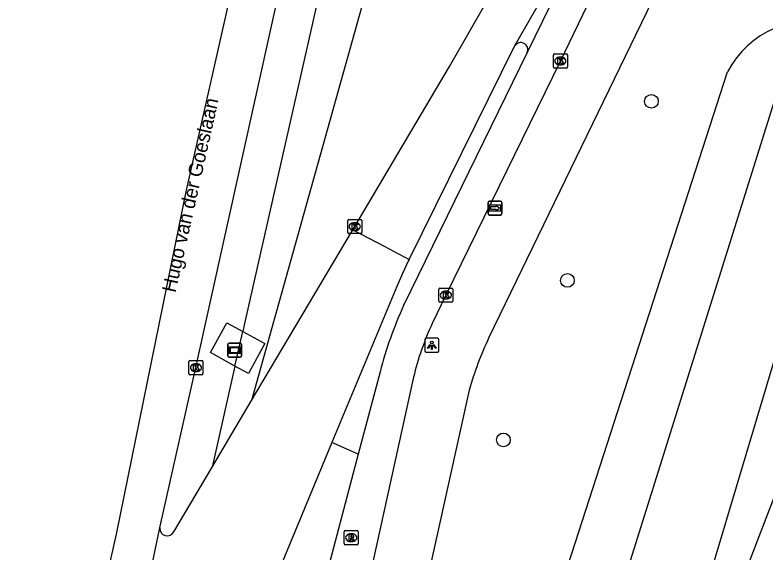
# Model space of a CAD drawing. Extents: x 163046 to 165074, y 382019 to 382874.
# Drawn here: x 163047.3 to 163100.8, y 382537 to 382575.3 of the extents above; entities that cross this region are included whole.
import ezdxf

# ---------------------------------------------------------------- set-up
doc = ezdxf.new("R2010")
doc.units = 0
for name, color, linetype in [('IMGEO_Berm_groen', 7, 'Continuous'), ('IMGEO_Boom', 7, 'Continuous'), ('IMGEO_Erf', 7, 'Continuous'), ('IMGEO_Fietspad_open', 7, 'Continuous'), ('IMGEO_Kolk', 7, 'Continuous'), ('IMGEO_Lichtpunt', 7, 'Continuous'), ('IMGEO_Openbare_ruimte_label', 7, 'Continuous'), ('IMGEO_Reclamebord', 7, 'Continuous'), ('IMGEO_Rijbaan_lokaal_gesloten', 7, 'Continuous'), ('IMGEO_Rijbaan_lokaal_open', 7, 'Continuous'), ('IMGEO_Rijbaan_regionaal_gesloten', 7, 'Continuous'), ('IMGEO_Rioolput', 7, 'Continuous'), ('IMGEO_Verkeerseiland_open', 7, 'Continuous'), ('IMGEO_Voetpad_open', 7, 'Continuous'), ('IMGEO_Waterloop', 7, 'Continuous'), ('IMGEO_Wegwijzer', 7, 'Continuous')]:
    doc.layers.add(name, color=color, linetype=linetype)

msp = doc.modelspace()

# ---------------------------------------------------------------- linework, layer by layer
at = {"layer": 'IMGEO_Berm_groen'}
for points in [[(163093.932, 382685.896), (163093.759, 382685.284), (163092.671, 382681.431), (163063.671, 382553.383), (163063.543, 382552.818)], [(163100.832, 382683.6), (163098.443, 382676.291), (163089.933, 382645.473), (163080.796, 382607.304), (163064.17, 382547.891)], [(163079.41, 382513.579), (163098.094, 382571.31)], [(163062.985, 382550.353), (163061.352, 382543.143)]]:
    msp.add_lwpolyline(points, dxfattribs=at)
msp.add_arc((163104.154, 382568.109), 6.853, 74.8139, 152.1561, dxfattribs=at)
at = {"layer": 'IMGEO_Boom'}
for centre in [(163092.668, 382569.203), (163086.678, 382556.45), (163082.117, 382545.088)]:
    msp.add_circle(centre, 0.489, dxfattribs=at)
at = {"layer": 'IMGEO_Erf'}
msp.add_lwpolyline([(163110.796, 382567.221), (163110.13, 382565.257), (163109.52, 382565.45), (163107.111, 382557.948), (163103.756, 382547.756), (163102.319, 382543.379), (163096.566, 382528.425), (163091.564, 382511.556)], dxfattribs=at)
at = {"layer": 'IMGEO_Fietspad_open'}
for points in [[(163090.329, 382586.006), (163083.814, 382572.678)], [(163092.391, 382584.969), (163091.883, 382583.941), (163086.165, 382572.05), (163078.013, 382555.397), (163077.04, 382553.381)], [(163083.814, 382572.678), (163075.006, 382554.656)], [(163073.328, 382549.944), (163071.757, 382544.071)], [(163075.706, 382549.562), (163070.131, 382524.198), (163067.388, 382511.786), (163064.83, 382500), (163063.356, 382493.212)], [(163071.757, 382544.071), (163069.665, 382536.151), (163067.191, 382524.864), (163064.403, 382512.197), (163062.59, 382503.776), (163061.753, 382500), (163060.171, 382492.863)]]:
    msp.add_lwpolyline(points, dxfattribs=at)
for centre, radius, start, end in [((163100.06, 382543.079), 27.599, 155.1995, 165.5977), ((163097.064, 382544.244), 22.01, 155.4726, 166.0182)]:
    msp.add_arc(centre, radius, start, end, dxfattribs=at)
at = {"layer": 'IMGEO_Kolk'}
for p, q in [((163085.677, 382571.649), (163085.677, 382572.501)), ((163085.752, 382572.575), (163086.604, 382572.575)), ((163086.165, 382572.355), (163086.19, 382572.355)), ((163086.678, 382572.501), (163086.678, 382571.649)), ((163086.188, 382571.795), (163086.163, 382571.795)), ((163086.604, 382571.575), (163085.752, 382571.575)), ((163071.02, 382559.854), (163071.02, 382560.706)), ((163071.095, 382560.78), (163071.947, 382560.78)), ((163071.508, 382560.56), (163071.533, 382560.56)), ((163072.021, 382560.706), (163072.021, 382559.854)), ((163071.531, 382560), (163071.506, 382560)), ((163071.947, 382559.78), (163071.095, 382559.78)), ((163077.517, 382554.98), (163077.517, 382555.832)), ((163077.592, 382555.906), (163078.444, 382555.906)), ((163078.518, 382555.832), (163078.518, 382554.98)), ((163078.005, 382555.686), (163078.03, 382555.686)), ((163078.444, 382554.906), (163077.592, 382554.906)), ((163078.028, 382555.126), (163078.003, 382555.126)), ((163059.702, 382549.81), (163059.702, 382550.662)), ((163059.777, 382550.736), (163060.629, 382550.736)), ((163060.19, 382550.516), (163060.215, 382550.516)), ((163060.703, 382550.662), (163060.703, 382549.81)), ((163060.213, 382549.956), (163060.188, 382549.956)), ((163060.629, 382549.736), (163059.777, 382549.736))]:
    msp.add_line(p, q, dxfattribs=at)
for points in [[(163085.677, 382571.649), (163085.677, 382572.501)], [(163085.752, 382572.575), (163086.604, 382572.575)], [(163086.678, 382572.501), (163086.678, 382571.649)], [(163085.998, 382572.275), (163086.121, 382572.275), (163086.121, 382572.124), (163086.251, 382572.275), (163086.415, 382572.275), (163086.269, 382572.124), (163086.422, 382571.875), (163086.27, 382571.875), (163086.185, 382572.039), (163086.121, 382571.972), (163086.121, 382571.875), (163085.998, 382571.875), (163085.998, 382572.275)], [(163086.604, 382571.575), (163085.752, 382571.575)], [(163071.02, 382559.854), (163071.02, 382560.706)], [(163071.095, 382560.78), (163071.947, 382560.78)], [(163072.021, 382560.706), (163072.021, 382559.854)], [(163071.341, 382560.48), (163071.464, 382560.48), (163071.464, 382560.329), (163071.594, 382560.48), (163071.758, 382560.48), (163071.612, 382560.329), (163071.765, 382560.08), (163071.613, 382560.08), (163071.528, 382560.244), (163071.464, 382560.177), (163071.464, 382560.08), (163071.341, 382560.08), (163071.341, 382560.48)], [(163071.947, 382559.78), (163071.095, 382559.78)], [(163077.517, 382554.98), (163077.517, 382555.832)], [(163077.592, 382555.906), (163078.444, 382555.906)], [(163078.518, 382555.832), (163078.518, 382554.98)], [(163077.838, 382555.606), (163077.961, 382555.606), (163077.961, 382555.455), (163078.091, 382555.606), (163078.255, 382555.606), (163078.109, 382555.455), (163078.262, 382555.206), (163078.11, 382555.206), (163078.025, 382555.37), (163077.961, 382555.303), (163077.961, 382555.206), (163077.838, 382555.206), (163077.838, 382555.606)], [(163078.444, 382554.906), (163077.592, 382554.906)], [(163059.702, 382549.81), (163059.702, 382550.662)], [(163059.777, 382550.736), (163060.629, 382550.736)], [(163060.023, 382550.436), (163060.146, 382550.436), (163060.146, 382550.285), (163060.276, 382550.436), (163060.44, 382550.436), (163060.294, 382550.285), (163060.447, 382550.036), (163060.295, 382550.036), (163060.21, 382550.2), (163060.146, 382550.133), (163060.146, 382550.036), (163060.023, 382550.036), (163060.023, 382550.436)], [(163060.703, 382550.662), (163060.703, 382549.81)], [(163060.629, 382549.736), (163059.777, 382549.736)]]:
    msp.add_lwpolyline(points, dxfattribs=at)
for centre, start, end in [((163085.754, 382572.499), 91.552, 178.448), ((163085.754, 382572.499), 91.552, 178.448), ((163086.602, 382572.499), 1.552, 88.448), ((163086.602, 382572.499), 1.552, 88.448), ((163085.754, 382571.651), 181.552, 268.448), ((163085.754, 382571.651), 181.552, 268.448), ((163086.602, 382571.651), 271.552, 358.448), ((163086.602, 382571.651), 271.552, 358.448), ((163071.097, 382560.704), 91.552, 178.448), ((163071.097, 382560.704), 91.552, 178.448), ((163071.945, 382560.704), 1.552, 88.448), ((163071.945, 382560.704), 1.552, 88.448), ((163071.097, 382559.856), 181.552, 268.448), ((163071.097, 382559.856), 181.552, 268.448), ((163071.945, 382559.856), 271.552, 358.448), ((163071.945, 382559.856), 271.552, 358.448), ((163077.594, 382555.83), 91.552, 178.448), ((163077.594, 382555.83), 91.552, 178.448), ((163078.442, 382555.83), 1.552, 88.448), ((163078.442, 382555.83), 1.552, 88.448), ((163077.594, 382554.982), 181.552, 268.448), ((163077.594, 382554.982), 181.552, 268.448), ((163078.442, 382554.982), 271.552, 358.448), ((163078.442, 382554.982), 271.552, 358.448), ((163059.779, 382550.66), 91.552, 178.448), ((163059.779, 382550.66), 91.552, 178.448), ((163060.627, 382550.66), 1.552, 88.448), ((163060.627, 382550.66), 1.552, 88.448), ((163059.779, 382549.812), 181.552, 268.448), ((163059.779, 382549.812), 181.552, 268.448), ((163060.627, 382549.812), 271.552, 358.448), ((163060.627, 382549.812), 271.552, 358.448)]:
    msp.add_arc(centre, 0.0765, start, end, dxfattribs=at)
for centre, major_axis, ratio, start_param, end_param in [((163086.164, 382572.075), (-0.387, 0.002), 0.722429, 4.712389, 7.853982), ((163086.189, 382572.075), (-0.39, 0.002), 0.717154, 1.570796, 4.712389), ((163071.507, 382560.28), (-0.387, 0.002), 0.722429, 4.712389, 7.853982), ((163071.532, 382560.28), (-0.39, 0.002), 0.717154, 1.570796, 4.712389), ((163078.004, 382555.406), (-0.387, 0.002), 0.722429, 4.712389, 7.853982), ((163078.029, 382555.406), (-0.39, 0.002), 0.717154, 1.570796, 4.712389), ((163060.189, 382550.236), (-0.387, 0.002), 0.722429, 4.712389, 7.853982), ((163060.214, 382550.236), (-0.39, 0.002), 0.717154, 1.570796, 4.712389)]:
    msp.add_ellipse(centre, major_axis=major_axis, ratio=ratio, start_param=start_param, end_param=end_param, dxfattribs=at)
at = {"layer": 'IMGEO_Lichtpunt'}
for p, q in [((163076.519, 382552.232), (163076.519, 382551.425)), ((163076.519, 382552.232), (163076.519, 382551.425)), ((163077.421, 382552.327), (163076.613, 382552.327)), ((163077.421, 382552.327), (163076.613, 382552.327)), ((163077.515, 382551.425), (163077.515, 382552.232)), ((163077.515, 382551.425), (163077.515, 382552.232)), ((163076.613, 382551.331), (163077.421, 382551.331)), ((163076.613, 382551.331), (163077.421, 382551.331))]:
    msp.add_line(p, q, dxfattribs=at)
for points in [[(163076.893, 382551.896), (163076.932, 382551.868), (163076.744, 382551.606), (163076.706, 382551.633), (163076.893, 382551.896)], [(163076.995, 382551.848), (163077.042, 382551.848), (163077.042, 382551.526), (163076.995, 382551.526), (163076.995, 382551.848)], [(163077.105, 382551.868), (163077.143, 382551.895), (163077.33, 382551.633), (163077.291, 382551.605), (163077.105, 382551.868)]]:
    msp.add_lwpolyline(points, dxfattribs=at)
msp.add_circle((163077.018, 382552.03), 0.0994, dxfattribs=at)
for centre, start, end in [((163076.613, 382552.232), 90, 180), ((163076.613, 382552.232), 90, 180), ((163077.421, 382552.232), 0, 90), ((163077.421, 382552.232), 0, 90), ((163076.613, 382551.425), 180, 270), ((163076.613, 382551.425), 180, 270), ((163077.421, 382551.425), 270, 0), ((163077.421, 382551.425), 270, 360)]:
    msp.add_arc(centre, 0.0946, start, end, dxfattribs=at)
at = {"layer": 'IMGEO_Reclamebord'}
for p, q in [((163062.567, 382551.981), (163063.357, 382551.981)), ((163063.357, 382551.981), (163062.567, 382551.981)), ((163062.467, 382551.081), (163062.467, 382551.881)), ((163062.467, 382551.881), (163062.467, 382551.081)), ((163063.457, 382551.881), (163063.457, 382551.081)), ((163063.457, 382551.081), (163063.457, 382551.881)), ((163063.357, 382550.981), (163062.567, 382550.981)), ((163062.567, 382550.981), (163063.357, 382550.981))]:
    msp.add_line(p, q, dxfattribs=at)
for points in [[(163062.568, 382551.713), (163063.356, 382551.713), (163063.356, 382551.249), (163062.568, 382551.249), (163062.568, 382551.713)], [(163062.633, 382551.648), (163062.633, 382551.314), (163063.291, 382551.314), (163063.291, 382551.648), (163062.633, 382551.648)]]:
    msp.add_lwpolyline(points, dxfattribs=at)
for centre, start, end in [((163062.567, 382551.881), 90, 180), ((163062.567, 382551.881), 90, 180), ((163063.357, 382551.881), 0, 90), ((163063.357, 382551.881), 360, 90), ((163062.567, 382551.081), 180, 270), ((163062.567, 382551.081), 180, 270), ((163063.357, 382551.081), 270, 0), ((163063.357, 382551.081), 270, 0)]:
    msp.add_arc(centre, 0.1, start, end, dxfattribs=at)
at = {"layer": 'IMGEO_Rijbaan_lokaal_gesloten'}
for points in [[(163064.17, 382547.891), (163071.394, 382560.063)], [(163071.394, 382560.063), (163073.608, 382558.885), (163075.39, 382557.937)], [(163075.39, 382557.937), (163075.337, 382557.831), (163074.917, 382556.943), (163074.517, 382556.019), (163069.894, 382544.912)], [(163061.352, 382543.143), (163064.17, 382547.891)], [(163069.894, 382544.912), (163058.472, 382517.403), (163057.328, 382514.544), (163053.768, 382506.009)], [(163058.622, 382538.547), (163061.352, 382543.143)]]:
    msp.add_lwpolyline(points, dxfattribs=at)
msp.add_arc((163058.154, 382538.778), 0.522, 175.1314, 333.7606, dxfattribs=at)
at = {"layer": 'IMGEO_Rijbaan_lokaal_open'}
for points in [[(163071.394, 382560.063), (163071.521, 382560.278), (163071.529, 382560.291), (163078.286, 382571.691), (163080.888, 382576.25), (163091.395, 382595.056)], [(163082.917, 382573.134), (163090.329, 382586.006)], [(163075.39, 382557.937), (163075.414, 382557.986), (163082.917, 382573.134)]]:
    msp.add_lwpolyline(points, dxfattribs=at)
at = {"layer": 'IMGEO_Rijbaan_regionaal_gesloten'}
for points in [[(163047.305, 382495.062), (163048.819, 382506.093), (163052.083, 382527.523), (163054.53, 382538.366), (163059.54, 382562.869), (163067.335, 382597.474), (163067.523, 382598.31), (163074.981, 382632.119), (163086.605, 382686.214), (163089.029, 382696.676)], [(163057.634, 382538.822), (163057.66, 382538.947), (163060.202, 382550.237), (163090.33, 382686.051)], [(163056.043, 382531.239), (163057.634, 382538.822)]]:
    msp.add_lwpolyline(points, dxfattribs=at)
at = {"layer": 'IMGEO_Rioolput'}
for p, q in [((163070.846, 382538.628), (163071.698, 382538.628)), ((163070.771, 382537.702), (163070.771, 382538.554)), ((163071.259, 382538.408), (163071.284, 382538.408)), ((163071.772, 382538.554), (163071.772, 382537.702)), ((163071.698, 382537.628), (163070.846, 382537.628)), ((163071.282, 382537.848), (163071.257, 382537.848))]:
    msp.add_line(p, q, dxfattribs=at)
for points in [[(163070.846, 382538.628), (163071.698, 382538.628)], [(163070.771, 382537.702), (163070.771, 382538.554)], [(163071.36, 382538.326), (163071.108, 382538.328), (163071.108, 382537.928)], [(163071.108, 382537.928), (163071.232, 382537.928), (163071.232, 382538.09), (163071.243, 382538.09)], [(163071.286, 382538.247), (163071.232, 382538.247), (163071.232, 382538.166)], [(163071.232, 382538.166), (163071.284, 382538.166)], [(163071.29, 382538.061), (163071.361, 382537.928), (163071.501, 382537.928), (163071.436, 382538.054)], [(163071.772, 382538.554), (163071.772, 382537.702)], [(163071.698, 382537.628), (163070.846, 382537.628)]]:
    msp.add_lwpolyline(points, dxfattribs=at)
for centre, radius, start, end in [((163070.848, 382538.552), 0.0765, 91.552, 178.448), ((163070.848, 382538.552), 0.0765, 91.552, 178.448), ((163071.696, 382538.552), 0.0765, 1.552, 88.448), ((163071.696, 382538.552), 0.0765, 1.552, 88.448), ((163071.242, 382538.037), 0.0533, 26.0293, 88.6989), ((163071.268, 382538.355), 0.19, 274.7715, 282.9687), ((163071.292, 382538.151), 0.0964, 77.0061, 93.1865), ((163071.306, 382538.208), 0.0378, 276.6634, 79.6772), ((163071.359, 382538.216), 0.109, 350.3612, 89.416), ((163071.357, 382538.216), 0.112, 277.5842, 350.9817), ((163071.341, 382538.001), 0.108, 29.5134, 73.7905), ((163070.848, 382537.704), 0.0765, 181.552, 268.448), ((163070.848, 382537.704), 0.0765, 181.552, 268.448), ((163071.696, 382537.704), 0.0765, 271.552, 358.448), ((163071.696, 382537.704), 0.0765, 271.552, 358.448)]:
    msp.add_arc(centre, radius, start, end, dxfattribs=at)
for centre, major_axis, ratio, start_param, end_param in [((163071.258, 382538.128), (-0.387, 0.002), 0.722429, 4.712389, 7.853982), ((163071.283, 382538.128), (-0.39, 0.002), 0.717154, 1.570796, 4.712389)]:
    msp.add_ellipse(centre, major_axis=major_axis, ratio=ratio, start_param=start_param, end_param=end_param, dxfattribs=at)
at = {"layer": 'IMGEO_Verkeerseiland_open'}
msp.add_lwpolyline([(163071.757, 382544.071), (163069.894, 382544.912)], dxfattribs=at)
msp.add_arc((163083.353, 382572.881), 0.504, 336.2724, 149.8336, dxfattribs=at)
at = {"layer": 'IMGEO_Voetpad_open'}
for points in [[(163097.844, 382586.779), (163095.46, 382582.022), (163081.09, 382552.378)], [(163062.985, 382550.353), (163061.239, 382551.304), (163062.402, 382553.439), (163063.543, 382552.818)], [(163063.543, 382552.818), (163065.11, 382551.964), (163063.947, 382549.829), (163062.985, 382550.353)], [(163062.985, 382550.353), (163063.543, 382552.818)], [(163079.679, 382548.626), (163073.606, 382521.183), (163070.492, 382506.972), (163068.968, 382500), (163065.947, 382486.176)]]:
    msp.add_lwpolyline(points, dxfattribs=at)
msp.add_arc((163101.675, 382542.495), 22.834, 154.3548, 164.426, dxfattribs=at)
at = {"layer": 'IMGEO_Waterloop'}
msp.add_lwpolyline([(163089.325, 382510.365), (163090.472, 382507.307), (163091.661, 382504.207), (163092, 382502.254), (163091.024, 382500.938), (163089.198, 382499.919), (163087.244, 382499.834), (163085.376, 382500.641), (163084.272, 382503.358), (163083.253, 382511.256), (163101.469, 382569.303), (163103.89, 382571.936), (163105.631, 382571.341), (163106.65, 382568.241), (163089.325, 382510.365)], dxfattribs=at)
at = {"layer": 'IMGEO_Wegwijzer'}
for p, q in [((163081.021, 382561.204), (163081.021, 382562.004)), ((163081.021, 382562.004), (163081.021, 382561.204)), ((163081.121, 382562.104), (163081.911, 382562.104)), ((163081.911, 382562.104), (163081.121, 382562.104)), ((163082.011, 382562.004), (163082.011, 382561.204)), ((163082.011, 382561.204), (163082.011, 382562.004)), ((163081.911, 382561.104), (163081.121, 382561.104)), ((163081.121, 382561.104), (163081.911, 382561.104))]:
    msp.add_line(p, q, dxfattribs=at)
for points in [[(163081.122, 382561.836), (163081.91, 382561.836), (163081.91, 382561.372), (163081.122, 382561.372), (163081.122, 382561.836)], [(163081.187, 382561.688), (163081.187, 382561.604), (163081.187, 382561.52), (163081.598, 382561.52), (163081.598, 382561.437), (163081.845, 382561.604), (163081.598, 382561.771), (163081.598, 382561.688), (163081.187, 382561.688)]]:
    msp.add_lwpolyline(points, dxfattribs=at)
for centre, start, end in [((163081.121, 382562.004), 90, 180), ((163081.121, 382562.004), 90, 180), ((163081.911, 382562.004), 0, 90), ((163081.911, 382562.004), 360, 90), ((163081.121, 382561.204), 180, 270), ((163081.121, 382561.204), 180, 270), ((163081.911, 382561.204), 270, 0), ((163081.911, 382561.204), 270, 0)]:
    msp.add_arc(centre, 0.1, start, end, dxfattribs=at)

# ---------------------------------------------------------------- texts
at = {"layer": 'IMGEO_Openbare_ruimte_label'}
msp.add_text('Hugo van der Goeslaan', height=1, rotation=77.409, dxfattribs=at).set_placement((163058.744, 382555.532))

doc.saveas('drawing.dxf')
